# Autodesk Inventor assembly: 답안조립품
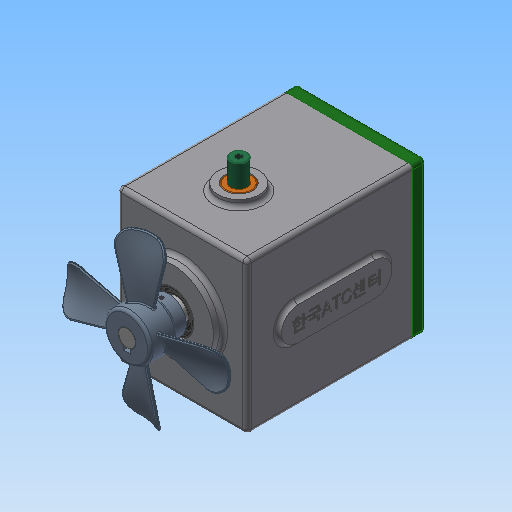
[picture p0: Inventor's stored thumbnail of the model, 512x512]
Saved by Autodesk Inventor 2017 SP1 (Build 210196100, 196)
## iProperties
Part Number: 답안조립품
Material: 일반
Document SubType Name: Assembly
Designer: MRC
Author: MRC
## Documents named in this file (17)
- C:\Users\MRC\Desktop\610205V1008\답안조립품.iam
- C:\Users\MRC\Desktop\610205V1008\본체.ipt
- C:\Users\MRC\Desktop\610205V1008\가변스프링.ipt
- C:\Users\MRC\Desktop\610205V1008\멈춤나사 M3x8.ipt
- C:\Users\MRC\Desktop\610205V1008\메인 기어 축.ipt
- C:\Users\MRC\Desktop\610205V1008\베어링 608.ipt
- C:\Users\MRC\Desktop\610205V1008\베어링 6903.ipt
- C:\Users\MRC\Desktop\610205V1008\볼트 M4 x 10.ipt
- C:\Users\MRC\Desktop\610205V1008\부시.ipt
- C:\Users\MRC\Desktop\610205V1008\서브 기어 축.ipt
- C:\Users\MRC\Desktop\610205V1008\슬라이더.ipt
- C:\Users\MRC\Desktop\610205V1008\오일 실 8 22 7.ipt
- C:\Users\MRC\Desktop\610205V1008\오일 실 17 30 8.ipt
- C:\Users\MRC\Desktop\610205V1008\커버.ipt
- C:\Users\MRC\Desktop\610205V1008\키 5 x 5 x 24.ipt
- C:\Users\MRC\Desktop\610205V1008\팬날개.ipt
- 팬날개.ipt
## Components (1 placed, 1 different names)
1. 가변스프링:1
